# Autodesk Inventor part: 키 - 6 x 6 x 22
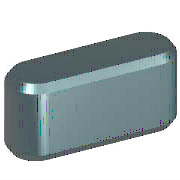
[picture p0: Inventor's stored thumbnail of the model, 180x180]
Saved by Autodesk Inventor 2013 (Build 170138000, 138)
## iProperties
IsCustomPart: 1
Created: 2012-02
Part Number: 키 - 6 x 6 x 22
Material: 강철, 연강
Description: 키 및 해당 키홈
Document SubType Name: Modeling
Standard: KS B 1311
Designer: mduedu
Standards Organization: KS
Language: ko-KR
Size Designation: 6 x 6 x 22
Categories: <MemberInstance><Categories><Category DisplayName="샤프트 부품" InternalName="7f7aeb1f-a693-4053-b835-cee3144e0d98" Mnemonic="SHFT"><Category DisplayName="키" Interna
Density: 7.86 g/cm^3
Mass: 5.79788 g
Surface Area: 5.294 cm^2
Volume: 0.737644 cm^3
Author: mduedu
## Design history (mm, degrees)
workplane "Work Plane1"
workplane "Work Plane2"
sketch "스케치1"
  geometry: L1 (3, 3)-(19, 3); L2 (19, -3)-(3, -3); L3 (0, 9.4)-(0, -7.4) reference; L4 (-5, 0)-(30, 0) reference; L5 (22, 0)-(22, 7); A1 r 3 centre (3, 0) between (3, 3) and (3, -3); A2 r 3 centre (19, 0) between (19, -3) and (19, 3)
  constraints: 6 end point, 5 point on circle, 4 tangent, 3 point on line, 2 centre point, 1 horizontal, 1 parallel, 1 perpendicular
  dimensions: "d0" = 3 radius of A1 (= 0.5 x PB); "d13" = 3 radius of A2 (= 0.5 x PB); "d14" = 22 distance between parallel lines of L5 L3 (= NLG)
extrude "본체1" new body sketch "스케치1" taper "d3" = 0 deg; stored distance "d4" = 10
workplane "Work Plane3"
body "Solid1"
chamfer "모따기1" distance "d8" = 0.4 (= PHH); stored, may be unused: second distance "d9" = 0.4 (= PHH), angle "d15" = 45 deg
other parameters: "d1" = -3.5 (= -PNT), "d2" = 2.5 (= PH - PNT), "NLG" = 22 [user parameter; used in 3 equation terms], "PB" = 6 [user parameter; used in 2 equation terms], "PNT" = 3.5 [user parameter; used in 2 equation terms], "PH" = 6 [user parameter; used in 1 equation term], "PHH" = 0.4 [user parameter; used in 2 equation terms], "d10" = 0, "d16" = 0, "d17" = 0, "d18" = 0, "WDMIN" = 17 [user parameter], "PLB2" = 22 (= NLG) [user parameter], "WDMAX" = 22 [user parameter], "PLB1" = 22 (= NLG) [user parameter], "RR" = 0.16 [user parameter], "PUEB" = 2.8 [user parameter]
